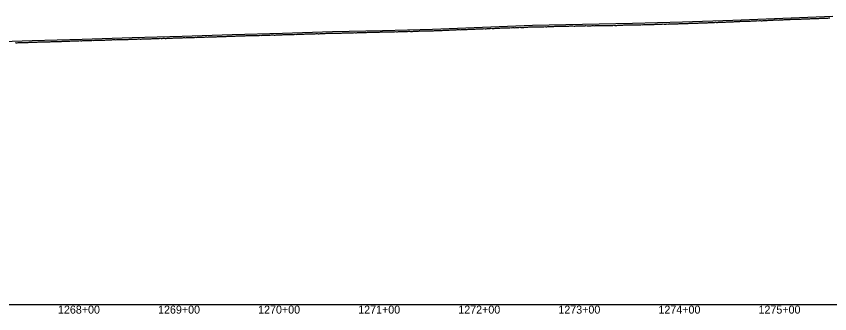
# Model space of a CAD drawing. Extents: x -3793 to 50787, y -1075 to 6138.
# Drawn here: x 14111 to 14924, y -1009 to -712 of the extents above; entities that cross this region are included whole.
import ezdxf

# ---------------------------------------------------------------- set-up
doc = ezdxf.new("R2010")
doc.units = 0
for name, color, linetype in [('RD_DDB_Profile_EX', 7, 'Continuous'), ('RD_DDB_Profile_PR', 7, 'Continuous'), ('RD_DDB_StaTX', 7, 'Continuous'), ('RD_GPK_Profile_Cell', 7, 'Continuous')]:
    doc.layers.add(name, color=color, linetype=linetype)

msp = doc.modelspace()

# ---------------------------------------------------------------- linework, layer by layer
at = {"layer": 'RD_DDB_Profile_EX'}
for points in [[(14784.888769, -718.892805), (14785.89274, -718.89037), (14786.89029, -718.83888), (14787.894073, -718.888845), (14788.891623, -718.84237), (14789.895757, -718.7449), (14790.893139, -718.690845), (14791.897273, -718.686885), (14792.894457, -718.63522), (14793.89202, -718.53762), (14794.896154, -718.490345), (14795.893536, -718.491525), (14796.897669, -718.39009), (14797.88787, -718.291475), (14798.891793, -718.338615), (14799.889372, -718.336905), (14801.099252, -718.332475), (14802.10337, -718.33243), (14803.107285, -718.232375), (14804.097462, -718.18381), (14805.101579, -718.13377), (14806.106653, -718.231125), (14807.110792, -718.18399), (14808.11493, -718.18103), (14809.111443, -718.227045), (14810.109065, -717.9324), (14811.105984, -718.028365), (14812.110124, -718.026865), (14813.113853, -717.832605), (14814.110773, -717.830045), (14815.108398, -717.7796), (14816.104908, -717.729945), (14817.109046, -717.77702), (14818.113185, -717.7784), (14819.109911, -717.628755), (14820.113838, -717.62871), (14821.104236, -717.58008), (14822.108184, -717.48287), (14823.104889, -717.43177), (14824.109027, -717.430315), (14825.113166, -717.477445), (14826.109891, -717.52367), (14827.107301, -717.428745), (14828.104212, -717.331895), (14829.108164, -717.177645), (14830.112303, -717.126185), (14831.109008, -717.17662), (14832.112961, -717.27378), (14833.103348, -717.22371), (14834.308574, -716.96778), (14835.111217, -716.92637), (14836.108107, -716.92682), (14837.112225, -716.92542), (14838.102384, -716.87266), (14839.106318, -716.822605), (14840.110436, -716.869815), (14841.107119, -716.72176), (14842.111057, -716.721695), (14843.10794, -716.77225), (14844.18595, -716.668955), (14845.10923, -716.62028), (14846.106073, -716.52093), (14847.11015, -716.518315), (14848.106618, -716.42161), (14849.110695, -716.371635), (14850.100995, -716.37166), (14851.105071, -716.3704), (14851.915889, -716.27171), (14852.91354, -716.369795), (14854.063325, -716.130585), (14854.91598, -716.165145), (14855.919788, -716.309725), (14856.917398, -716.30903), (14857.914825, -716.25975), (14858.918627, -716.014195), (14859.916242, -715.962145), (14860.913863, -715.961525), (14861.917687, -715.96162), (14862.915084, -715.909525), (14863.9407, -715.810695), (14864.917402, -715.85597), (14865.921132, -715.75934), (14866.91871, -715.707225), (14867.916083, -715.655045), (14868.920049, -715.60686), (14869.91739, -715.561185), (14870.914762, -715.412315), (14871.919648, -715.45614), (14872.923361, -715.64798), (14873.920948, -715.599055), (14874.918268, -715.35538), (14875.922183, -715.355665), (14876.91947, -715.35353), (14877.916789, -715.303045), (14878.920704, -715.210255), (14879.918254, -715.16161), (14880.922583, -715.198095), (14881.920137, -715.147605), (14882.924053, -715.04972), (14883.921087, -715.049265), (14884.918593, -715.05071)], [(14884.918593, -715.05071), (14885.922458, -714.904715), (14886.902417, -714.906195), (14887.899546, -714.90584), (14888.904203, -714.94918), (14889.907943, -714.949535), (14890.905072, -714.852905), (14891.902461, -714.75636), (14892.9062, -714.70101), (14893.903321, -714.698755), (14894.900693, -714.648475), (14895.90441, -714.697025), (14896.316995, -714.500275), (14897.314245, -714.592285), (14898.311495, -714.497745), (14899.316323, -714.40067), (14900.319834, -714.447165), (14901.317082, -714.30473), (14902.31489, -714.302485), (14903.450202, -714.29819), (14904.322913, -714.29601), (14905.320365, -714.149835), (14906.317556, -714.147615), (14907.314747, -714.1474), (14908.312203, -714.05128), (14909.315645, -714.049735), (14910.320146, -713.9968), (14911.317603, -713.996615), (14912.314794, -714.044345), (14913.327577, -714.089375), (14914.315636, -713.944765), (14915.320072, -713.89389), (14916.317205, -713.850005), (14917.321172, -713.80055), (14918.318305, -713.70043), (14919.315709, -713.696205), (14920.312843, -713.696075), (14921.317279, -713.69313), (14922.320929, -713.69169), (14923.318056, -713.545735), (14924.315132, -713.5436)], [(14585.923406, -723.86275), (14586.920646, -723.954315), (14587.924657, -723.995515), (14588.922555, -723.95), (14589.925937, -723.9), (14590.923216, -723.895375), (14591.921131, -723.804695), (14592.925184, -723.704685), (14593.702914, -723.65), (14594.706985, -723.61425), (14595.710373, -723.568915), (14596.707896, -723.55926), (14597.705707, -723.52352), (14598.70845, -723.50469), (14599.705968, -723.454595), (14600.71004, -723.45458), (14601.707171, -723.454645), (14602.704669, -723.40455), (14603.707456, -723.404535), (14604.711529, -723.4), (14605.702737, -723.259025), (14606.706155, -723.29551), (14607.709606, -723.163465), (14608.707095, -723.16317), (14609.704228, -723.336635), (14610.708299, -723.245555), (14611.70514, -723.06735), (14612.708612, -723.054335), (14613.706372, -722.958815), (14614.703212, -722.921505), (14615.707284, -722.971445), (14616.711355, -723.05), (14617.701285, -722.95), (14618.705356, -723), (14619.708815, -722.808465), (14620.706268, -722.80827), (14621.70401, -722.766835), (14622.706893, -722.66259), (14623.710966, -722.61255), (14624.708412, -722.52043), (14625.705546, -722.608305), (14626.709617, -722.56242), (14627.706484, -722.466195), (14628.703618, -722.46235), (14629.70769, -722.416415), (14630.704531, -722.36999), (14631.708051, -722.415975), (14632.705763, -722.44593), (14633.702604, -722.492075), (14634.706675, -722.35), (14635.710747, -722.3), (14636.700676, -722.296075), (14637.704748, -722.296085), (14638.708256, -722.296105), (14639.705661, -722.211385), (14640.703356, -722.3), (14641.706334, -722.284565), (14642.703733, -722.24248), (14643.753531, -722.15366), (14644.757094, -722.09636), (14645.75456, -721.95354), (14646.751024, -722), (14647.755109, -722.15), (14648.752544, -722.05666), (14649.756055, -721.8594), (14650.753022, -721.85608), (14651.757107, -721.853025), (14652.754067, -721.80876), (14653.751429, -721.758455), (14654.755113, -721.8028), (14655.752079, -721.897295), (14656.74941, -721.8974), (14657.759791, -721.80249), (14658.757106, -721.75239), (14659.754392, -721.65457), (14660.751031, -721.70218), (14661.755116, -721.70217), (14662.752076, -721.65618), (14663.749314, -721.65), (14664.761386, -721.6), (14665.764522, -721.6), (14666.761048, -721.50329), (14667.757774, -721.50308), (14668.761602, -721.65), (14669.758308, -721.64858), (14670.754809, -721.501315), (14671.758838, -721.55), (14672.755334, -721.4012), (14673.758276, -721.499005), (14674.754892, -721.550885), (14675.758806, -721.501745), (14676.755402, -721.451525), (14677.751879, -721.401955), (14678.755907, -721.40128), (14679.752379, -721.352115), (14680.748847, -721.252915), (14681.759405, -721.40091), (14682.755881, -721.35057), (14683.752362, -721.3503), (14684.405175, -721.317245), (14684.749158, -721.30019)], [(14684.749158, -721.30019), (14685.753297, -721.30024), (14686.750746, -721.200815), (14687.748194, -721.20137), (14688.752335, -721.30135), (14689.75721, -721.252045), (14690.754677, -721.20268), (14691.752124, -721.153595), (14692.756264, -721.253015), (14693.753711, -721.20397), (14694.751154, -721.05505), (14695.755257, -721.104265), (14696.752741, -721.154435), (14697.757631, -721.205675), (14698.755077, -721.15493), (14699.689089, -721.20456), (14700.685752, -721.105455), (14701.689898, -721.0059), (14702.687391, -721.00639), (14703.684107, -721.15481), (14704.688139, -721.104045), (14705.692285, -721.05449), (14706.682349, -721.05371), (14707.686495, -721.00333), (14708.690585, -720.85462), (14709.687303, -721.002765), (14710.684797, -721.102565), (14711.688943, -721.10302), (14712.693031, -720.80479), (14713.683158, -720.803515), (14714.687179, -720.753985), (14715.691325, -720.70402), (14716.68799, -720.654215), (14717.685541, -720.654545), (14718.689626, -720.55504), (14719.686349, -720.5539), (14720.683844, -720.604195), (14721.68799, -720.55329), (14722.692073, -720.552845), (14723.688798, -720.602245), (14724.686222, -720.50289), (14725.690367, -720.454365), (14726.687094, -720.4523), (14727.684589, -720.50197), (14728.689017, -720.50149), (14729.685664, -720.451415), (14730.689813, -720.45095), (14731.687395, -720.5), (14732.684039, -720.5), (14733.688115, -720.5), (14734.692263, -720.40049), (14735.689778, -720.300525), (14736.686492, -720.2505), (14737.690574, -720.2995), (14738.68808, -720.201605), (14739.684796, -720.102545), (14740.688877, -720.15154), (14741.693025, -720.251035), (14742.683109, -720.2), (14743.687179, -720.00105), (14744.691328, -720.00053), (14745.688843, -720.001125), (14746.685562, -719.95161), (14747.885498, -720.04946), (14748.882961, -720.048855), (14749.88701, -719.850575), (14750.884394, -719.80061), (14751.888528, -719.9), (14752.885913, -719.851295), (14753.890046, -719.8487), (14754.887422, -719.800685), (14755.891463, -719.899315), (14756.88894, -719.84784), (14757.885689, -719.6), (14758.883172, -719.64782), (14759.880664, -719.69772), (14760.884582, -719.69771), (14761.882074, -719.59841), (14762.8861, -719.6468), (14763.883597, -719.598335), (14764.887731, -719.54749), (14765.884991, -719.49826), (14766.889124, -719.49651), (14767.886508, -719.397285), (14768.890642, -719.39909), (14769.888153, -719.39906), (14770.892019, -719.445275), (14771.88953, -719.34609), (14772.893531, -719.29607), (14773.891047, -719.246955), (14774.895181, -719.245925), (14775.892564, -719.244745), (14776.889934, -719.194585), (14777.886688, -719.19259), (14778.884219, -719.044545), (14779.888353, -719.141245), (14780.885741, -719.139855), (14781.889707, -719.138695), (14782.88709, -719.18604), (14783.891224, -718.943), (14784.888769, -718.892805)], [(14288.472815, -733.150875), (14289.470376, -733.05165), (14290.474716, -732.90214), (14291.478877, -732.952065), (14292.468909, -732.901975), (14293.473071, -732.85215), (14294.47722, -732.85214), (14295.467252, -732.85222), (14296.4714, -732.802405), (14297.475562, -732.802385), (14298.479723, -732.802355), (14299.469759, -732.70278), (14300.473921, -732.60311), (14301.478048, -732.60271), (14302.475694, -732.70327), (14303.472264, -732.553525), (14304.476409, -732.4539), (14305.474061, -732.503675), (14306.47061, -732.45312), (14307.47475, -732.4532), (14308.47238, -732.45374), (14309.476542, -732.354185), (14310.473116, -732.40329), (14311.477257, -732.354015), (14312.474913, -732.20541), (14313.471463, -732.203865), (14314.267897, -732.2046), (14315.264847, -732.15419), (14316.26196, -732.1056), (14317.266063, -732.00591), (14318.270165, -732.005155), (14319.260157, -732.055245), (14320.26426, -732.005335), (14321.268299, -731.955425), (14322.265444, -731.90595), (14323.262394, -731.805605), (14324.266497, -731.755935), (14325.263648, -731.806205), (14326.267713, -731.75657), (14327.264663, -731.755965), (14328.261776, -731.705905), (14329.265879, -731.7057), (14330.269941, -731.706065), (14331.259983, -731.606725), (14332.264087, -731.606815), (14333.268148, -731.606905), (14334.26526, -731.557315), (14335.262211, -731.50769), (14336.266313, -731.407785), (14337.263427, -731.3586), (14338.260422, -731.307975), (14339.264525, -731.40742), (14340.261592, -731.35817), (14341.265695, -731.258975), (14342.262645, -731.20835), (14343.25981, -731.209165), (14344.263914, -731.15926), (14345.267964, -731.15973), (14346.257978, -731.159445), (14347.262027, -731.10916), (14348.26613, -731.05925), (14349.263244, -731.010455), (14350.260249, -731.00983), (14351.264352, -731.010715), (14352.261471, -730.96031), (14353.265512, -730.96126), (14354.262462, -730.960205), (14355.259638, -730.91058), (14356.263679, -731.00934), (14357.267782, -730.860765), (14358.25787, -730.81176), (14359.261845, -730.81049), (14360.265947, -730.761035), (14361.269985, -730.760665), (14362.260077, -730.66075), (14363.264114, -730.660845), (14364.268217, -730.660455), (14365.265329, -730.611165), (14366.038184, -730.561085), (14367.042304, -730.56117), (14368.032352, -730.56126), (14369.036472, -730.659865), (14370.040524, -730.610445), (14371.035623, -730.460855), (14372.039662, -730.46047), (14373.036798, -730.41169), (14374.033731, -730.3616), (14375.037836, -730.31218), (14376.034833, -730.41155), (14377.031904, -730.362365), (14378.03601, -730.261465), (14379.033008, -730.21041), (14380.037048, -730.210975), (14381.041084, -730.16154), (14382.031184, -730.16114), (14383.035222, -730.160745), (14384.039327, -730.06329), (14385.036258, -730.0126), (14386.040297, -730.06083), (14387.030394, -730.159965), (14388.0345, -730.01052)], [(14388.0345, -730.01052), (14389.038539, -729.961095), (14390.03547, -729.910965), (14391.032675, -729.96126), (14392.036712, -729.91135), (14393.03371, -729.910305), (14394.037749, -729.86038), (14395.034681, -729.858935), (14396.031886, -729.76007), (14397.035992, -729.711115), (14398.032855, -729.760075), (14399.03696, -729.71016), (14400.041066, -729.561175), (14401.031096, -729.56033), (14402.035134, -729.51088), (14403.039239, -729.51097), (14404.036172, -729.460845), (14405.033377, -729.459695), (14406.030304, -729.4101), (14407.034346, -729.409725), (14408.038451, -729.40887), (14409.035384, -729.358835), (14410.032588, -729.310445), (14411.036625, -729.21291), (14412.033557, -729.26042), (14413.037663, -729.35914), (14414.034655, -729.3082), (14415.031731, -729.210215), (14416.035837, -729.21077), (14417.032831, -729.160185), (14418.036874, -729.20849), (14419.040915, -729.158555), (14420.031006, -728.95999), (14421.035048, -728.911455), (14421.569367, -728.910775), (14422.573443, -728.909125), (14423.570141, -728.859005), (14424.574281, -728.86033), (14425.57103, -728.809305), (14426.568483, -728.85842), (14427.56517, -728.8583), (14428.569311, -728.80838), (14429.566004, -728.75785), (14430.570145, -728.80755), (14431.566831, -728.70774), (14432.570925, -728.658185), (14433.567664, -728.755945), (14434.571806, -728.75635), (14435.56845, -728.70648), (14436.572591, -728.65656), (14437.569324, -728.606025), (14438.573426, -728.45698), (14439.570115, -728.50583), (14440.567605, -728.55656), (14441.564295, -728.456275), (14442.568437, -728.45553), (14443.565126, -728.55452), (14444.569229, -728.50484), (14445.565952, -728.40458), (14446.56264, -728.45346), (14447.566782, -728.40373), (14448.563466, -728.30381), (14449.565697, -728.254075), (14450.562648, -728.35303), (14451.56675, -728.402775), (14452.563683, -728.152885), (14453.567784, -728.10339), (14454.564756, -728.20254), (14455.561866, -728.15327), (14456.558835, -728.15258), (14457.562921, -728.202285), (14458.559872, -728.10212), (14459.563974, -728.002305), (14460.560926, -728.001655), (14461.565028, -728.05157), (14462.561979, -727.90125), (14463.566073, -727.851455), (14464.563033, -727.900695), (14465.567135, -727.90077), (14466.564087, -727.850265), (14467.568187, -727.900295), (14468.19819, -727.836805), (14468.565263, -727.80023), (14469.569316, -727.750115), (14470.559229, -727.750025), (14471.50008, -727.75048), (14472.705754, -727.710485), (14473.494019, -727.75014), (14474.498043, -727.650225), (14475.502078, -727.600305), (14476.499487, -727.550925), (14477.496009, -727.550055), (14478.493445, -727.600215), (14479.49745, -727.600185), (14480.501201, -727.60024), (14481.498321, -727.550505), (14482.502379, -727.500625), (14483.492358, -727.45057), (14484.496417, -727.45026), (14485.500496, -727.350585), (14486.497576, -727.35103)], [(14486.497576, -727.35103), (14487.501657, -727.350575), (14488.498581, -727.350235), (14489.4957, -727.300665), (14490.499758, -727.25077), (14491.496888, -727.450245), (14492.500935, -727.35046), (14493.497875, -727.20069), (14494.494984, -727.150815), (14495.499063, -727.150765), (14496.496173, -727.15112), (14497.500252, -727.1008), (14498.497159, -727.100305), (14499.494268, -727.050725), (14500.498315, -727.050915), (14501.495456, -727.001585), (14502.499493, -727.05061), (14503.503573, -726.90175), (14504.493552, -726.901395), (14505.497631, -726.950795), (14506.501675, -727.000505), (14507.49882, -727.000685), (14508.502853, -726.90099), (14509.492881, -726.90095), (14510.496916, -726.702125), (14511.500953, -726.70116), (14512.49805, -726.7519), (14513.502131, -726.7022), (14514.492121, -726.603185), (14515.4962, -726.602725), (14516.500233, -726.500985), (14517.497388, -726.550835), (14518.501411, -726.55081), (14519.491461, -726.55039), (14520.495485, -726.55), (14521.499564, -726.50073), (14522.496674, -726.45137), (14523.500753, -726.350885), (14524.50471, -726.30086), (14525.494769, -726.300835), (14526.498791, -726.35081), (14527.495958, -726.35148), (14528.49997, -726.301925), (14529.50405, -726.251405), (14529.919606, -726.15139), (14530.917832, -726.150555), (14531.916004, -726.151285), (14532.919927, -726.10189), (14533.926351, -726.002465), (14534.924613, -725.953645), (14535.922781, -725.951), (14536.926538, -726.000985), (14537.924691, -725.858605), (14538.922978, -725.80814), (14539.915847, -725.75345), (14540.913314, -725.70495), (14541.917819, -725.70428), (14542.915323, -725.75151), (14543.91915, -725.74701), (14544.916448, -725.601585), (14545.913972, -725.558355), (14546.911518, -725.55878), (14547.915073, -725.503485), (14548.919732, -725.451925), (14549.917299, -725.5), (14550.921079, -725.452), (14551.918349, -725.25832), (14552.915936, -725.26082), (14553.913242, -725.21126), (14554.917292, -725.304475), (14555.914568, -725.252315), (14556.9189, -725.205), (14557.922952, -725.10746), (14558.920592, -725.05514), (14559.917504, -725.0553), (14560.915165, -725.155465), (14561.919215, -725.10544), (14562.916104, -724.914), (14563.913784, -724.861525), (14564.924789, -724.90296), (14565.92249, -724.85), (14566.919329, -724.659365), (14567.91705, -724.6532), (14568.921101, -724.656375), (14569.918401, -724.653275), (14570.915658, -724.556695), (14571.926592, -724.45685), (14572.923878, -724.54649), (14573.921649, -724.55359), (14574.9189, -724.45366), (14575.922458, -724.446345), (14576.920248, -724.35373), (14577.918059, -724.40381), (14578.921035, -724.265185), (14579.925644, -724.35396), (14580.923473, -724.287885), (14581.920768, -724.11649), (14582.924213, -724.162305), (14583.922061, -724.187465), (14584.919354, -724.05), (14585.923406, -723.86275)], [(14110.478701, -738.21092), (14111.482794, -738.309125), (14112.486912, -738.35887), (14113.484614, -738.2597), (14114.481144, -738.15978), (14115.485261, -738.209155), (14116.482964, -738.11078), (14117.479035, -738.061285), (14118.483609, -738.059815), (14119.481314, -738.010675), (14120.485478, -738.06036), (14121.489525, -738.01087), (14122.486122, -737.96021), (14123.483829, -737.96064), (14124.479369, -737.861595), (14125.484471, -737.909695), (14126.482179, -737.860925), (14127.486343, -737.81102), (14128.490382, -737.71156), (14129.480529, -737.711655), (14130.484693, -737.76085), (14131.488798, -737.71049), (14132.477319, -737.71057), (14133.481401, -737.56204), (14134.485552, -737.56214), (14135.489632, -737.51223), (14136.479773, -737.46233), (14137.48379, -737.51147), (14138.48794, -737.512525), (14139.485463, -737.3144), (14140.482163, -737.31369), (14141.486314, -737.36429), (14142.483841, -737.31576), (14143.480539, -737.3135), (14144.484614, -737.362085), (14145.488765, -737.312175), (14146.486292, -737.165115), (14147.482924, -737.21493), (14148.486997, -737.16451), (14149.484601, -737.163775), (14150.481224, -737.11366), (14151.485375, -737.06323), (14152.4829, -737.015165), (14153.487051, -737.0147), (14154.483674, -737.012955), (14155.487825, -737.012505), (14156.485273, -736.963835), (14157.481983, -736.91433), (14158.486051, -736.86442), (14159.483659, -736.81468), (14160.487809, -736.764775), (14161.484433, -736.76414), (14162.482047, -736.764955), (14163.054947, -736.71561), (14164.051863, -736.76437), (14165.049104, -736.765795), (14166.053124, -736.56527), (14167.057146, -736.515375), (14168.047196, -736.56484), (14169.051304, -736.51493), (14170.055321, -736.415635), (14171.052328, -736.41501), (14172.049481, -736.415815), (14173.053588, -736.364635), (14174.057604, -736.316635), (14175.04775, -736.268015), (14176.051675, -736.31812), (14177.055782, -736.36432), (14178.045838, -736.2657), (14179.049945, -736.16645), (14180.054053, -736.11588), (14181.058064, -736.067295), (14182.048218, -736.11672), (14183.052229, -736.066805), (14184.056337, -735.968925), (14185.046396, -736.01766), (14186.050409, -736.017085), (14187.054418, -735.96648), (14188.051669, -735.91798), (14189.048586, -736.01665), (14190.052693, -735.91604), (14191.0567, -735.86682)], [(14191.0567, -735.86682), (14192.053952, -735.866865), (14193.05087, -735.81699), (14194.054977, -735.76708), (14195.052025, -735.717855), (14196.049049, -735.716535), (14197.053053, -735.61806), (14198.050308, -735.61811), (14199.054307, -735.617435), (14200.051333, -735.616125), (14201.05544, -735.467685), (14202.052592, -735.46768), (14203.049616, -735.516365), (14204.053616, -735.46793), (14205.050772, -735.467935), (14206.054766, -735.418795), (14207.051796, -735.318195), (14208.048947, -735.26896), (14209.053055, -735.22143), (14210.049972, -735.26614), (14211.054079, -735.315445), (14212.051231, -735.26688), (14213.055795, -735.21777), (14214.052811, -735.11879), (14214.402534, -735.11881), (14215.399102, -735.167445), (14216.403261, -735.11753), (14217.399829, -735.06769), (14218.396505, -735.114955), (14219.400555, -735.06574), (14220.397228, -735.014505), (14221.401282, -734.96527), (14222.397952, -735.01405), (14223.394516, -734.96481), (14224.398675, -734.86619), (14225.395158, -734.864945), (14226.391816, -734.863155), (14227.395884, -734.813225), (14228.392452, -734.813245), (14229.396611, -734.71507), (14230.393178, -734.713305), (14231.389826, -734.71112), (14232.393904, -734.661725), (14233.390549, -734.563205), (14234.387112, -734.56255), (14235.397759, -734.708695), (14236.394326, -734.60908), (14237.390955, -734.558965), (14238.395052, -734.50986), (14239.391677, -734.409645), (14240.395778, -734.359345), (14241.392345, -734.408375), (14242.388963, -734.35746), (14243.393071, -734.30788), (14244.389686, -734.3573), (14245.386249, -734.406135), (14246.390408, -734.306215), (14247.386971, -734.20568), (14248.391095, -734.155765), (14249.387662, -734.15548), (14250.384262, -734.105375), (14251.388387, -734.10546), (14252.384984, -734.104655), (14253.381547, -734.053895), (14254.385679, -733.954155), (14255.382269, -733.90373), (14256.378831, -733.953125), (14257.389523, -733.952415), (14258.386089, -733.80199), (14259.390248, -733.851835), (14260.386814, -733.95116), (14261.383385, -734.00072), (14262.387539, -733.80098), (14263.384106, -733.800265), (14263.81747, -733.73477), (14264.381417, -733.650105), (14265.385377, -733.650115), (14266.383248, -733.65013), (14267.471862, -733.65), (14268.475835, -733.6001), (14269.654602, -733.54085), (14270.469687, -733.500225), (14271.473676, -733.45012), (14271.989357, -733.424115), (14272.470489, -733.400395), (14273.474639, -733.40045), (14274.471501, -733.45006), (14275.538072, -733.39686), (14276.472957, -733.350765), (14277.469567, -733.30014), (14278.473718, -733.250245), (14279.471271, -733.20096), (14280.475417, -733.301), (14281.472034, -733.250465), (14282.469585, -733.151215), (14283.473738, -733.201245), (14284.477881, -733.151445), (14285.467909, -733.051595), (14286.472051, -733.10135), (14287.476204, -733.151425), (14288.472815, -733.150875)]]:
    msp.add_lwpolyline(points, dxfattribs=at)
at = {"layer": 'RD_DDB_Profile_PR'}
msp.add_lwpolyline([(14077.33, -737.6515), (14127.33, -736.219), (14177.33, -734.737), (14227.33, -733.2165), (14277.33, -731.707), (14327.33, -730.1525), (14377.33, -728.7325), (14427.33, -727.2585), (14477.33, -725.95), (14527.33, -724.7515), (14577.33, -722.7745), (14627.33, -720.9025), (14677.33, -719.823), (14727.33, -718.8845), (14777.33, -717.5935), (14827.33, -715.807), (14877.33, -713.7325), (14927.33, -711.8935)], dxfattribs=at)
at = {"layer": 'RD_GPK_Profile_Cell'}
msp.add_line((1000, -1000), (46610.921919, -1000), dxfattribs=at)

# ---------------------------------------------------------------- texts
at = {"layer": 'RD_DDB_StaTX'}
for s, p in [('1268+00', (14153.125471, -1009)), ('1268+00', (14153.125471, -1009)), ('1269+00', (14253.125471, -1009)), ('1269+00', (14253.125471, -1009)), ('1270+00', (14353.125471, -1009)), ('1270+00', (14353.125471, -1009)), ('1271+00', (14453.125471, -1009)), ('1271+00', (14453.125471, -1009)), ('1272+00', (14553.125471, -1009)), ('1272+00', (14553.125471, -1009)), ('1273+00', (14653.125471, -1009)), ('1273+00', (14653.125471, -1009)), ('1274+00', (14753.125471, -1009)), ('1274+00', (14753.125471, -1009)), ('1275+00', (14853.125471, -1009)), ('1275+00', (14853.125471, -1009))]:
    msp.add_text(s, height=8, dxfattribs=at).set_placement(p)

doc.saveas('drawing.dxf')
